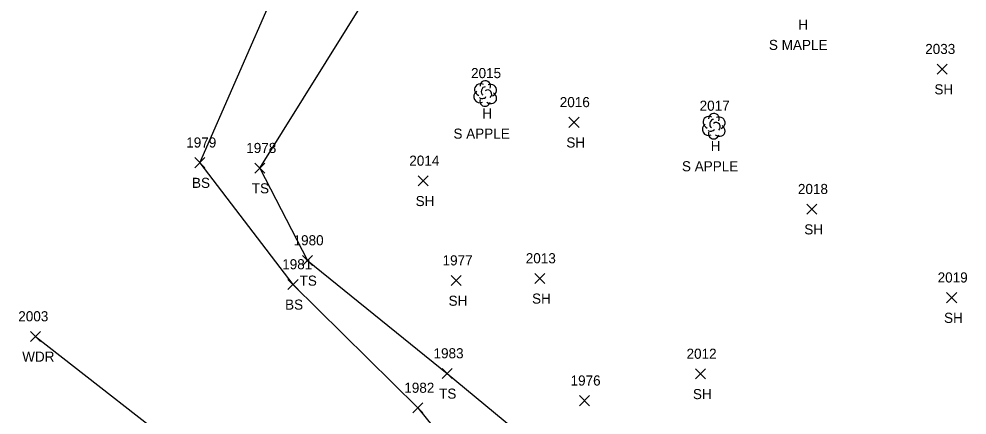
# Model space of a CAD drawing. Extents: x 1885914 to 1887218, y 756253 to 760620.
# Drawn here: x 1886282.6 to 1886470.3, y 759954.5 to 760033 of the extents above; entities that cross this region are included whole.
import ezdxf

# ---------------------------------------------------------------- set-up
doc = ezdxf.new("R2010")
doc.units = 0
for name, color, linetype in [('L_A', 7, 'Continuous'), ('L_C', 7, 'Continuous'), ('L_I', 7, 'Continuous'), ('L_TIC', 7, 'Continuous'), ('LAWA', 7, 'Continuous'), ('LELB', 7, 'Continuous'), ('LTD', 7, 'Continuous')]:
    doc.layers.add(name, color=color, linetype=linetype)

msp = doc.modelspace()

# ---------------------------------------------------------------- linework, layer by layer
at = {"layer": 'L_TIC'}
for points in [[(1886464.34, 760022.01), (1886466.34, 760024.01)], [(1886466.34, 760022.01), (1886464.34, 760024.01)], [(1886391.47, 760011.48), (1886393.47, 760013.48)], [(1886393.47, 760011.48), (1886391.47, 760013.48)], [(1886317.4, 760003.48), (1886319.4, 760005.48)], [(1886319.4, 760003.48), (1886317.4, 760005.48)], [(1886317.4, 760003.48), (1886319.4, 760005.48)], [(1886319.4, 760003.48), (1886317.4, 760005.48)], [(1886329.28, 760002.4), (1886331.28, 760004.4)], [(1886331.28, 760002.4), (1886329.28, 760004.4)], [(1886329.28, 760002.4), (1886331.28, 760004.4)], [(1886331.28, 760002.4), (1886329.28, 760004.4)], [(1886361.63, 759999.88), (1886363.63, 760001.88)], [(1886363.63, 759999.88), (1886361.63, 760001.88)], [(1886438.57, 759994.27), (1886440.57, 759996.27)], [(1886440.57, 759994.27), (1886438.57, 759996.27)], [(1886338.73, 759984.11), (1886340.73, 759986.11)], [(1886340.73, 759984.11), (1886338.73, 759986.11)], [(1886384.69, 759980.55), (1886386.69, 759982.55)], [(1886386.69, 759980.55), (1886384.69, 759982.55)], [(1886335.83, 759979.36), (1886337.83, 759981.36)], [(1886337.83, 759979.36), (1886335.83, 759981.36)], [(1886368.14, 759980.13), (1886370.14, 759982.13)], [(1886370.14, 759980.13), (1886368.14, 759982.13)], [(1886466.24, 759976.74), (1886468.24, 759978.74)], [(1886468.24, 759976.74), (1886466.24, 759978.74)], [(1886284.87, 759969.05), (1886286.87, 759971.05)], [(1886286.87, 759969.05), (1886284.87, 759971.05)], [(1886366.35, 759961.72), (1886368.35, 759963.72)], [(1886368.35, 759961.72), (1886366.35, 759963.72)], [(1886416.53, 759961.63), (1886418.53, 759963.63)], [(1886418.53, 759961.63), (1886416.53, 759963.63)], [(1886393.54, 759956.32), (1886395.54, 759958.32)], [(1886395.54, 759956.32), (1886393.54, 759958.32)], [(1886360.56, 759954.89), (1886362.56, 759956.89)], [(1886362.56, 759954.89), (1886360.56, 759956.89)]]:
    msp.add_lwpolyline(points, dxfattribs=at)
at = {"layer": 'LAWA'}
msp.add_lwpolyline([(1886285.87, 759970.05), (1886318.69, 759944.4), (1886343.23, 759929.77), (1886350.74, 759901.14), (1886371.48, 759869.99)], dxfattribs=at)
at = {"layer": 'LELB'}
for points in [[(1886330.28, 760003.4), (1886352.03, 760038.4), (1886370.3, 760059.83), (1886371.46, 760066.43), (1886371.59, 760074.58), (1886374.31, 760083.29)], [(1886318.4, 760004.48), (1886340.79, 760055.64)], [(1886318.4, 760004.48), (1886336.83, 759980.36), (1886361.56, 759955.89), (1886382.85, 759929.46), (1886414.19, 759903.62), (1886402.13, 759873.85), (1886423.52, 759862.16), (1886432.91, 759869.01)], [(1886330.28, 760003.4), (1886339.73, 759985.11), (1886367.35, 759962.72), (1886393.37, 759941.16), (1886421.61, 759906.02), (1886432.44, 759885.61), (1886426.62, 759873.12), (1886408.74, 759874.79), (1886424.64, 759865.71), (1886432.91, 759869.01)]]:
    msp.add_lwpolyline(points, dxfattribs=at)
at = {"layer": 'LTD'}
for p, q in [((1886374.86, 760018.23), (1886374.86, 760018.23)), ((1886374.86, 760018.23), (1886374.86, 760018.23)), ((1886420.11, 760011.77), (1886420.11, 760011.77)), ((1886420.11, 760011.77), (1886420.11, 760011.77))]:
    msp.add_line(p, q, dxfattribs=at)
for centre in [(1886374.91, 760019.66), (1886420.16, 760013.2)]:
    msp.add_arc(centre, 1.05, 335.5272, 180.9563, dxfattribs=at)
for centre, major_axis, ratio, start_param, end_param in [((1886374.07, 760018.89), (1.21, -0.51), 0.895232, 1.570796, 4.712389), ((1886375.91, 760018.81), (-1.14, -0.48), 0.949671, 1.570796, 4.712389), ((1886373.78, 760017.52), (0.58, -1.04), 0.959034, 3.141593, 6.283185), ((1886374.66, 760018.69), (-0.208, -0.792), 0.645439, 3.141593, 6.283185), ((1886375.36, 760018.06), (-0.5, 0.667), 0.989748, 3.141593, 6.283185), ((1886375.87, 760017.39), (-1.09, 0.79), 0.841452, 1.570796, 4.712389), ((1886374.87, 760016.73), (0.26, 1.06), 0.942809, 1.570796, 4.712389), ((1886374.41, 760017.48), (-0.625, -0.083), 0.423636, 0, 3.141593), ((1886419.32, 760012.43), (1.21, -0.51), 0.895232, 1.570796, 4.712389), ((1886419.9, 760012.23), (-0.208, -0.792), 0.645439, 3.141593, 6.283185), ((1886420.61, 760011.6), (-0.5, 0.667), 0.989748, 3.141593, 6.283185), ((1886421.15, 760012.35), (-1.14, -0.48), 0.949671, 1.570796, 4.712389), ((1886419.03, 760011.06), (0.58, -1.04), 0.959034, 3.141593, 6.283185), ((1886420.11, 760010.27), (0.26, 1.06), 0.942809, 1.570796, 4.712389), ((1886419.65, 760011.02), (-0.625, -0.083), 0.423636, 0, 3.141593), ((1886421.11, 760010.93), (-1.09, 0.79), 0.841452, 1.570796, 4.712389)]:
    msp.add_ellipse(centre, major_axis=major_axis, ratio=ratio, start_param=start_param, end_param=end_param, dxfattribs=at)

# ---------------------------------------------------------------- texts
at = {"layer": 'L_A'}
for s, p in [('H', (1886436.89, 760030.81)), ('SH', (1886463.82, 760018.01)), ('H', (1886374.3, 760013.23)), ('SH', (1886390.96, 760007.48)), ('H', (1886419.54, 760006.77)), ('BS', (1886316.84, 759999.48)), ('BS', (1886316.84, 759999.48)), ('TS', (1886328.68, 759998.4)), ('TS', (1886328.68, 759998.4)), ('SH', (1886361.12, 759995.88)), ('SH', (1886438.06, 759990.27)), ('TS', (1886338.14, 759980.11)), ('SH', (1886384.17, 759976.55)), ('BS', (1886335.27, 759975.36)), ('SH', (1886367.63, 759976.13)), ('SH', (1886465.73, 759972.74)), ('WDR', (1886283.23, 759965.05)), ('TS', (1886365.76, 759957.72)), ('SH', (1886416.01, 759957.63))]:
    msp.add_text(s, height=2, dxfattribs=at).set_placement(p)
at = {"layer": 'L_C'}
for s, p in [('S MAPLE', (1886431.06, 760026.81)), ('S APPLE', (1886368.6, 760009.23)), ('S APPLE', (1886413.84, 760002.77))]:
    msp.add_text(s, height=2, dxfattribs=at).set_placement(p)
at = {"layer": 'L_I'}
for s, p in [('2033', (1886462, 760026.01)), ('2015', (1886372.09, 760021.23)), ('2016', (1886389.65, 760015.48)), ('2017', (1886417.34, 760014.77)), ('1979', (1886315.7, 760007.48)), ('1979', (1886315.7, 760007.48)), ('1978', (1886327.58, 760006.4)), ('1978', (1886327.58, 760006.4)), ('2014', (1886359.86, 760003.88)), ('2018', (1886436.8, 759998.27)), ('1980', (1886336.95, 759988.11)), ('1977', (1886366.45, 759984.13)), ('2013', (1886382.92, 759984.55)), ('1981', (1886334.7, 759983.36)), ('2019', (1886464.46, 759980.74)), ('2003', (1886282.45, 759973.05)), ('1983', (1886364.66, 759965.72)), ('2012', (1886414.75, 759965.63)), ('1976', (1886391.79, 759960.32)), ('1982', (1886358.87, 759958.89))]:
    msp.add_text(s, height=2, dxfattribs=at).set_placement(p)

doc.saveas('drawing.dxf')
